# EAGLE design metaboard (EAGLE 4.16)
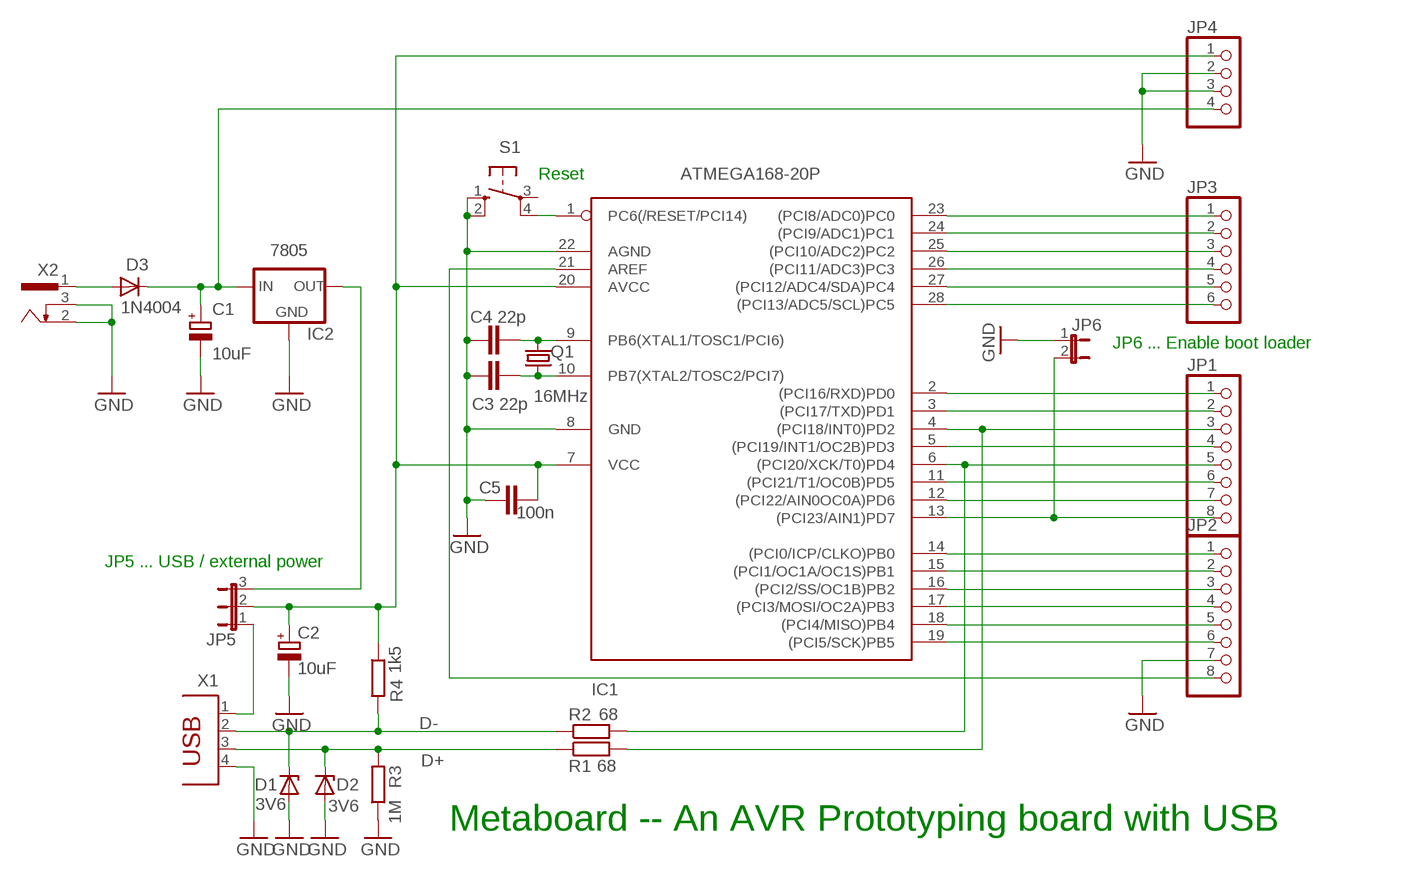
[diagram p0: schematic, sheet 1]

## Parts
C1  10uF  CPOL-EUE2,5-6E  [E2,5-6E]
C2  10uF  CPOL-EUE2,5-6E  [E2,5-6E]
C3  22p  C-EU025-024X044  [C025-024X044]
C4  22p  C-EU025-024X044  [C025-024X044]
C5  100n  C-EU025_050-025X075  [C025_050-025X075]
D1  3V6  ZENER-DIODEDO34-7  [DO34Z7]
D2  3V6  ZENER-DIODEDO34-7  [DO34Z7]
D3  1N4004  [DO41-10]
IC1  ATMEGA168-20P  [DIL28-3]
IC2  7805  78XXL  [78XXL]
JP1  PINHD-1X8  [1X08]
JP2  PINHD-1X8  [1X08]
JP3  PINHD-1X6  [1X06]
JP4  PINHD-1X4  [1X04]
JP5  JP2E  [JP2]
JP6  JP1E  [JP1]
Q1  16MHz  CRYSTALHC49S  [HC49/S]
R1  68  R-EU_0207/10  [0207/10]
R2  68  R-EU_0207/10  [0207/10]
R3  1M  R-EU_0207/10  [0207/10]
R4  1k5  R-EU_0207/10  [0207/10]
S1  10-XX  [B3F-10XX]
X1  PN61729  [PN61729]
X2  733980-62  [733980-62]

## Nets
+5USB: JP5.1 X1.1
+5V: C2.+ C5.2 IC1.7(VCC) IC1.20(AVCC) JP4.1 JP5.2 R4.1
+VRAW: C1.+ D3.C IC2.IN JP4.4
D+: D2.C R1.1 R3.2 X1.3
D-: D1.C R2.1 R4.2 X1.2
GND: C1.- C2.- C3.1 C4.1 C5.1 D1.A D2.A IC1.8(GND) IC1.22(AGND) IC2.GND JP2.7 JP4.2 JP4.3 JP6.1 R3.1 S1.1(S) S1.2(S1) X1.4 X2.2 X2.3
N$1: IC1.6((PCI20/XCK/T0)PD4) JP1.5 R2.2
N$2: IC1.1(PC6(/RESET/PCI14)) S1.4(P1)
N$3: IC1.4((PCI18/INT0)PD2) JP1.3 R1.2
N$4: D3.A X2.1
N$6: IC1.2((PCI16/RXD)PD0) JP1.1
N$8: IC2.OUT JP5.3
N$9: C3.2 IC1.10(PB7(XTAL2/TOSC2/PCI7)) Q1.1
N$10: C4.2 IC1.9(PB6(XTAL1/TOSC1/PCI6)) Q1.2
N$11: IC1.3((PCI17/TXD)PD1) JP1.2
N$12: IC1.5((PCI19/INT1/OC2B)PD3) JP1.4
N$13: IC1.11((PCI21/T1/OC0B)PD5) JP1.6
N$14: IC1.12((PCI22/AIN0OC0A)PD6) JP1.7
N$15: IC1.13((PCI23/AIN1)PD7) JP1.8 JP6.2
N$16: IC1.23((PCI8/ADC0)PC0) JP3.1
N$17: IC1.24((PCI9/ADC1)PC1) JP3.2
N$18: IC1.25((PCI10/ADC2)PC2) JP3.3
N$19: IC1.26((PCI11/ADC3)PC3) JP3.4
N$20: IC1.27((PCI12/ADC4/SDA)PC4) JP3.5
N$21: IC1.28((PCI13/ADC5/SCL)PC5) JP3.6
N$22: IC1.14((PCI0/ICP/CLKO)PB0) JP2.1
N$23: IC1.15((PCI1/OC1A/OC1S)PB1) JP2.2
N$24: IC1.16((PCI2/SS/OC1B)PB2) JP2.3
N$25: IC1.17((PCI3/MOSI/OC2A)PB3) JP2.4
N$26: IC1.18((PCI4/MISO)PB4) JP2.5
N$27: IC1.19((PCI5/SCK)PB5) JP2.6
N$28: IC1.21(AREF) JP2.8
Unconnected: S1.3(P)

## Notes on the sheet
- Reset
- JP6 ... Enable boot loader
- JP5 ... USB / external power
- Metaboard -- An AVR Prototyping board with USB

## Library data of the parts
C1 C2 = rcl:CPOL-EU: POLARIZED CAPACITOR, European symbol
C3-C5 = rcl:C-EU: CAPACITOR, European symbol
D1 D2 = diode:ZENER-DIODE: Z-Diode
D3 = diode:1N4004: DIODE
IC1 = avr:ATMEGA168*P: MICROCONTROLLER 16 kBytes FLASH 1 kBytes SRAM 512 Bytes EEPROM USART 8-channel 10 bit ADC
IC2 = v-reg:78XXL: VOLTAGE REGULATOR
JP1 JP2 = pinhead:PINHD-1X8: PIN HEADER
JP3 = pinhead:PINHD-1X6: PIN HEADER
JP4 = pinhead:PINHD-1X4: PIN HEADER
JP5 = jumper:JP2E: JUMPER
JP6 = jumper:JP1E: JUMPER
Q1 = crystal:CRYSTAL: CRYSTAL
R1-R4 = rcl:R-EU_: RESISTOR, European symbol
S1 = switch-omron:10-XX: OMRON SWITCH
X1 = con-berg:PN61729: BERG USB connector
X2 = con-conrad:73398?: FEMALE PRINT CONNECTOR Niedervolt-Steckverbinder Distributor Conrad

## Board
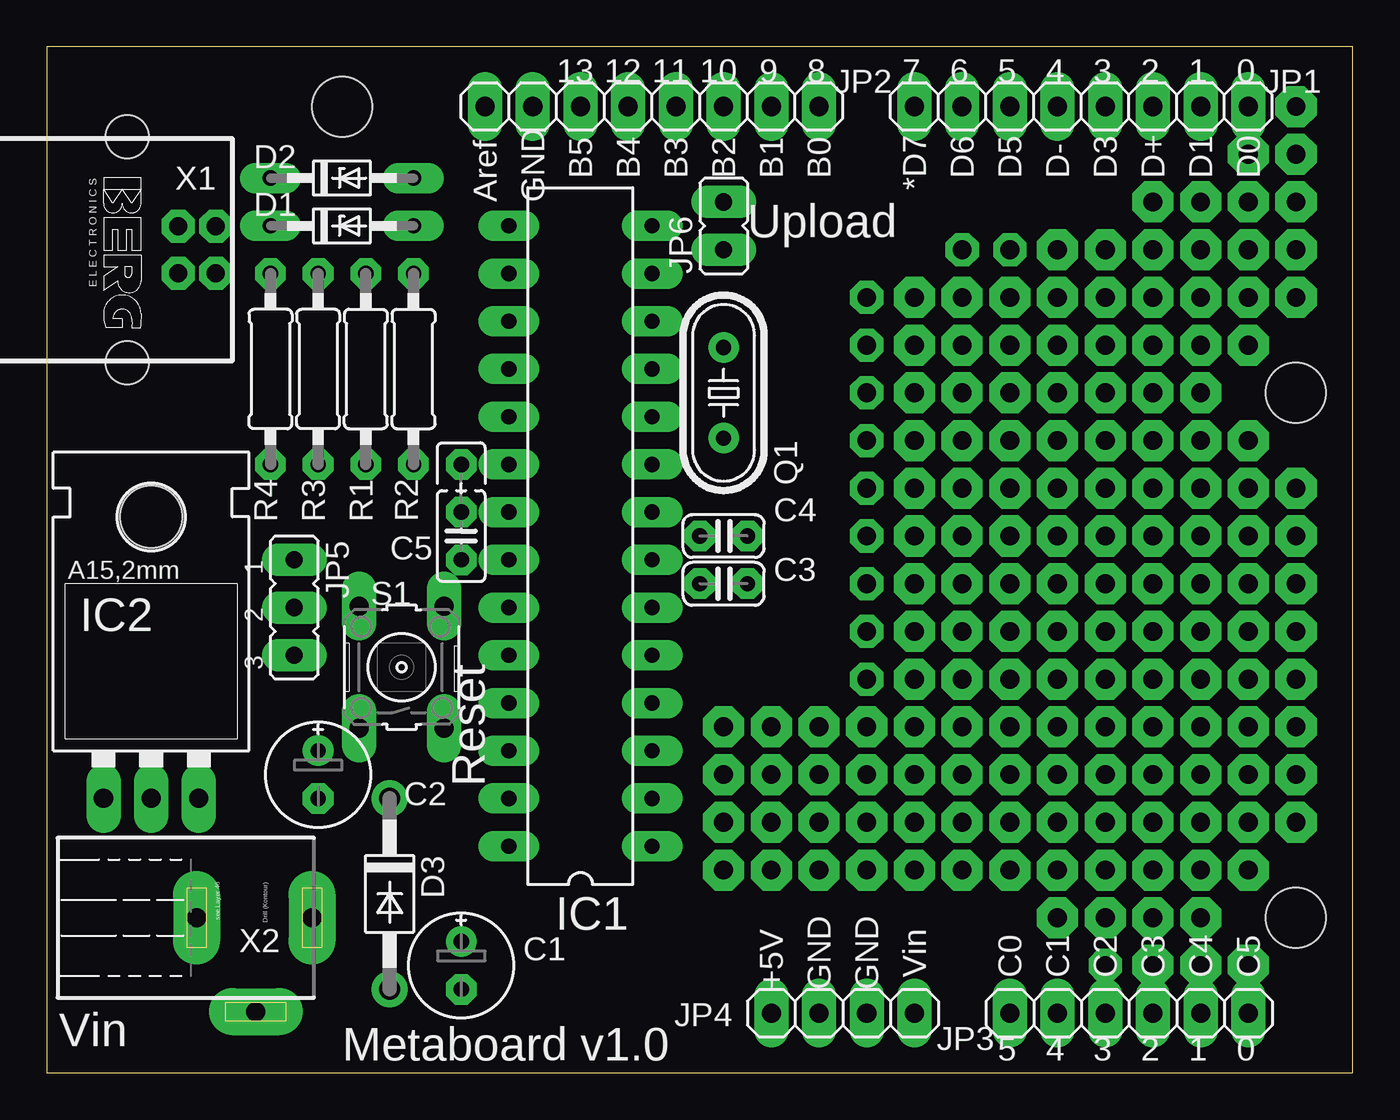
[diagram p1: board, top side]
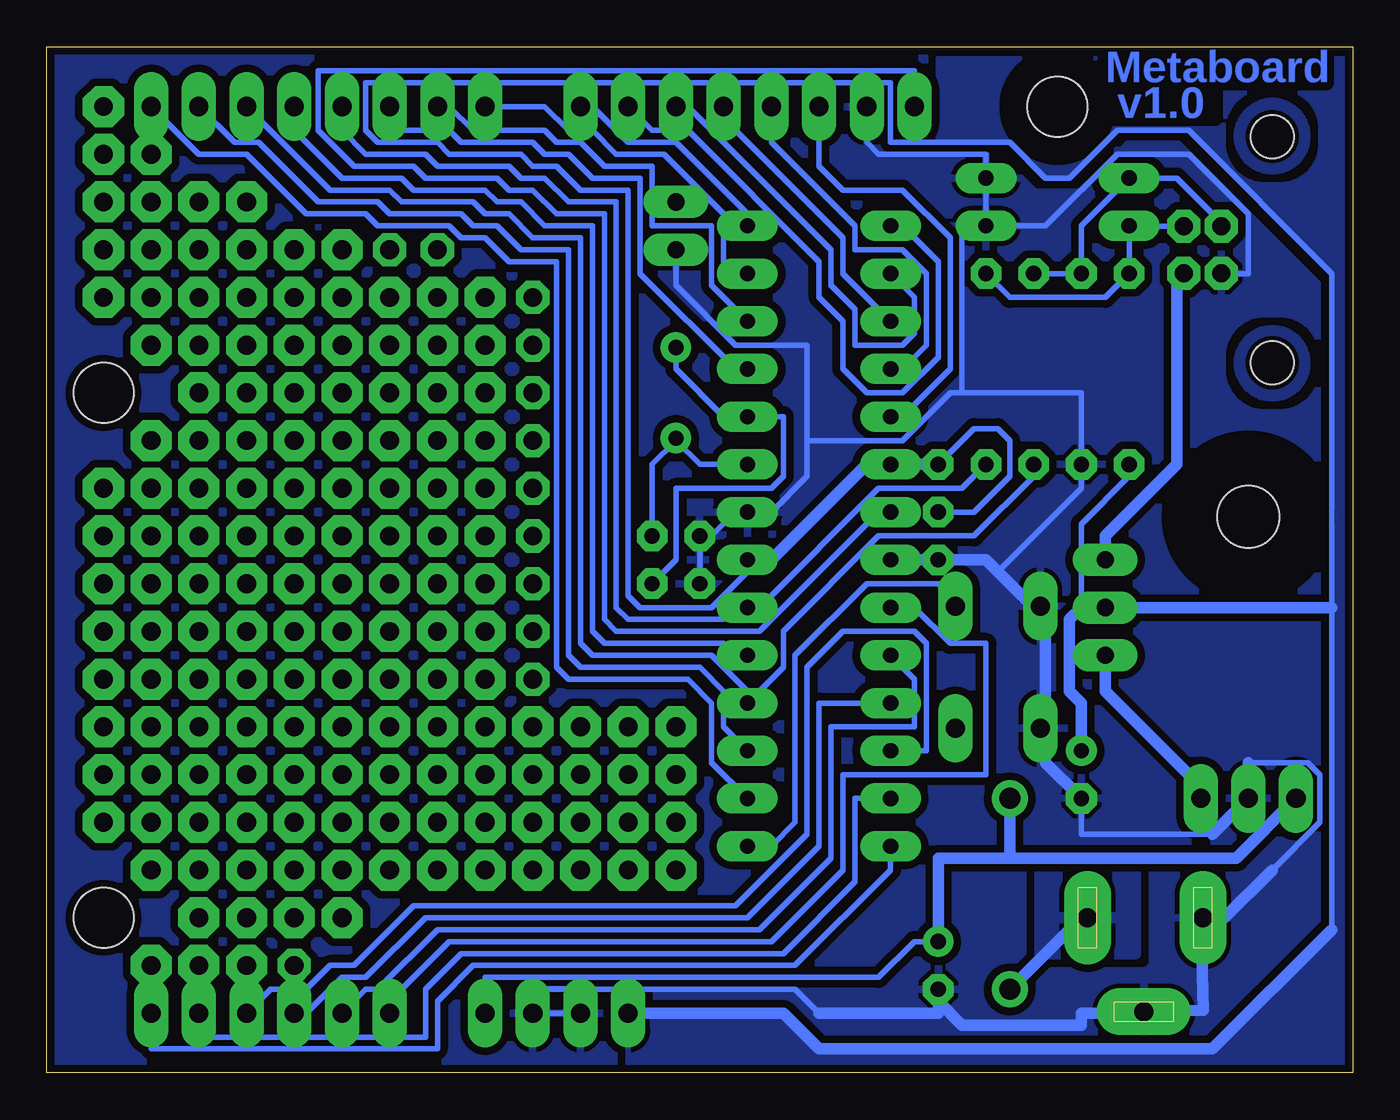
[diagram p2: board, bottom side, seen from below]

Size 69.52 x 54.6 mm. Coordinates in mm from the lower left corner, seen from the top.
Outline: 0,0 69.52,0 69.52,54.6 0,54.6 0,0
Copper layers (1*16): Top 0.035mm / dielectric 1.5mm / Bottom 0.035mm
Design rules "mine": minimum track width 12mil, minimum drill 31mil, track to track 8mil, track to pad 8mil, pad to pad 8mil, via to via 8mil, smd to smd 8mil, copper to edge 10mil, drill to drill 20mil, minimum pad ring 16mil, minimum via ring 15mil, stop-mask expansion 4mil, vias tented up to drill 0mil, thermal gap 10mil
Holes 3.2 mm at 66.51,36.19 66.51,8.25 15.71,51.43
bRestrict: area 13,48.7 to 18.4,54.1

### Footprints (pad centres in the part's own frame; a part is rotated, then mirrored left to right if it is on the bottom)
E2,5-6E = drill 0.813 pad 1.575 round: + -1.27,0 | drill 0.813 pad 1.575 octagon: - 1.27,0
C025-024X044 = drill 0.813 octagon: 1 -1.27,0; 2 1.27,0
C025_050-025X075 = drill 0.813 octagon: 1 -1.27,0; 2 1.27,0; 3 3.81,0
DO34Z7 = drill 0.813 long: A 3.81,0; C -3.81,0
DO41-10 = drill 1.118 round: A 5.08,0; C -5.08,0
DIL28-3 = drill 0.813 long: 1 -16.51,-3.81; 2 -13.97,-3.81; 3 -11.43,-3.81; 4 -8.89,-3.81; 5 -6.35,-3.81; 6 -3.81,-3.81; 7 -1.27,-3.81; 8 1.27,-3.81; 9 3.81,-3.81; 10 6.35,-3.81; 11 8.89,-3.81; 12 11.43,-3.81; 13 13.97,-3.81; 14 16.51,-3.81; 15 16.51,3.81; 16 13.97,3.81; 17 11.43,3.81; 18 8.89,3.81; 19 6.35,3.81; 20 3.81,3.81; 21 1.27,3.81; 22 -1.27,3.81; 23 -3.81,3.81; 24 -6.35,3.81; 25 -8.89,3.81; 26 -11.43,3.81; 27 -13.97,3.81; 28 -16.51,3.81
78XXL = drill 1.016 long: GND 0,-3.81; IN -2.54,-3.81; OUT 2.54,-3.81 | hole 3.302: 0,11.176
1X08 = drill 1.016 long: 1 -8.89,0; 2 -6.35,0; 3 -3.81,0; 4 -1.27,0; 5 1.27,0; 6 3.81,0; 7 6.35,0; 8 8.89,0
1X06 = drill 1.016 long: 1 -6.35,0; 2 -3.81,0; 3 -1.27,0; 4 1.27,0; 5 3.81,0; 6 6.35,0
1X04 = drill 1.016 long: 1 -3.81,0; 2 -1.27,0; 3 1.27,0; 4 3.81,0
JP2 = drill 0.914 long: 1 -2.54,0; 2 0,0; 3 2.54,0
JP1 = drill 0.914 long: 1 0,-1.27; 2 0,1.27
HC49/S = drill 0.813 round: 1 -2.413,0; 2 2.413,0
0207/10 = drill 0.813 octagon: 1 -5.08,0; 2 5.08,0
B3F-10XX = drill 1.016 long: 1 -3.251,2.261; 2 3.251,2.261; 3 -3.251,-2.261; 4 3.251,-2.261
PN61729 = drill 0.95 octagon: 1 1.25,4.71; 2 -1.25,4.71; 3 -1.25,2.71; 4 1.25,2.71 | hole 2.3: -6.02,0; 6.02,0
733980-62 = drill 1 pad 2.5 long: 1 0,8.57; 2 0,2.42; 3 5,5.57

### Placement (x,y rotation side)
C1  22.06,5.71 270 top
C2  14.44,15.87 270 top
C3  36.03,26.03 0 top
C4  36.03,28.57 0 top
C5  22.06,28.57 90 top
D1  15.71,45.08 0 top
D2  15.71,47.62 0 top
D3  18.25,9.52 270 top
IC1  28.41,28.57 90 top
IC2  5.55,18.41 0 top
JP1  55.08,51.43 180 top
JP2  32.22,51.43 180 top
JP3  57.62,3.17 0 top
JP4  42.38,3.17 0 top
JP5  13.17,24.76 270 top
JP6  36.03,45.08 0 top
Q1  36.03,36.19 270 top
R1  16.98,37.46 270 top
R2  19.52,37.46 270 top
R3  14.44,37.46 90 top
R4  11.9,37.46 90 top
S1  18.88,21.58 90 top
X1  4.28,43.81 270 top
X2  5.55,8.25 270 top

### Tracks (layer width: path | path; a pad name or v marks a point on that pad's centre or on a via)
+5USB
  Bottom 0.61: JP5.1 13.17,28.57 9.36,32.38 9.36,41.91 X1.1
+5V
  Bottom 0.305: IC1.7 32.22,26.66 34.12,24.76 37.94,24.76 38.57,25.39 38.57,46.98 41.11,46.98 42.38,48.26 43.65,48.26 44.28,48.89 48.09,48.89 48.73,49.53 51.91,49.53 52.54,50.16 52.54,52.7 24.6,52.7 24.6,49.53 18.25,49.53 16.34,47.62 15.08,47.62 12.54,50.16 8.73,50.16 1.1,42.54 1.1,24.76 1.1,7.62 | 14.44,24.76 14.44,29.2 11.9,31.74 R4.1 | C5.2 20.15,29.84 18.25,31.74 18.25,33.65 18.88,34.29 20.15,34.29 22.06,32.38
  Bottom 0.61: IC1.7 30.95,27.3 25.87,32.38 IC1.20 22.06,32.38 | JP4.1 30.31,3.17 28.41,1.27 7.46,1.27 1.1,7.62 | C2.+ 14.44,19.68 15.08,20.31 15.08,24.12 14.44,24.76 JP5.2 1.1,24.76
  pour Bottom (isolate 0.406): 0.47,42.54 0.47,7.62 1.1,7.62 1.1,42.54
  pour Bottom (isolate 0.406, rank 2): 0.47,42.54 0.47,53.97 22.06,53.97 22.06,49.53 18.25,49.53 16.34,47.62 15.08,47.62 12.54,50.16 8.73,50.16 1.1,42.54
  pour Bottom (isolate 0.406, rank 2): 1.74,6.98 7.46,1.27 28.41,1.27 30.31,3.17 38.57,3.17 38.57,-0.01 -0.17,-0.01 -0.17,7.62 1.1,7.62
+VRAW
  Bottom 0.305: JP4.4 46.19,5.08 25.23,5.08 23.33,6.98 C1.+
  Bottom 0.61: IC2.IN 6.18,11.43 18.25,11.43 | 18.25,11.43 22.06,11.43 C1.+ | 18.25,11.43 D3.C
D+
  Bottom 0.305: R1.1 R3.2 14.44,45.08 D2.C 9.36,47.62 6.99,45.25 X1.3
D-
  Bottom 0.305: R2.1 18.25,41.27 13.17,41.27 R4.2 11.88,42.56 11.88,45.06 | 11.88,45.06 X1.2 | 11.88,45.06 D1.C
GND
  Bottom 0.305: C5.1 IC1.22 | JP4.3 JP4.2 41.11,4.44 29.68,4.44 28.41,3.17 | C2.- 14.44,12.7 7.46,12.7 | 5.55,16.5 2.38,16.5 1.74,15.87 1.74,13.33 4.28,10.79 | C3.1 C4.1 34.12,28.57 32.85,29.84 IC1.8 30.95,29.84 29.04,31.74 29.04,33.65 | JP6.1 36.03,41.91 32.85,38.73 29.04,38.73 29.04,33.65 | 29.04,33.65 23.96,33.65 21.42,36.19 20.79,36.19 | JP2.7 25.87,49.53 25.23,48.89 19.52,48.89 D2.A | 20.79,36.19 14.44,36.19 R3.1 14.44,31.11 18.88,26.66 | 20.79,36.19 20.79,45.08 D1.A | D1.A D2.A | D1.A D2.A | D1.A 16.34,45.08 12.54,48.89 8.73,48.89 5.55,45.72 5.55,42.54 6.82,42.54 X1.4
  Bottom 0.308: 41.11,4.44 43.65,4.44 JP4.3
  Bottom 0.61: IC1.22 C5.1 19.52,27.3 18.88,26.66 16.98,24.76 | S1.2 16.9,24.84 16.98,24.76 | 16.98,24.76 16.34,24.12 16.34,18.41 | S1.1 16.42,18.33 16.34,18.41 | 16.34,18.41 16.34,16.5 C2.- | 28.41,3.17 22.06,3.17 C1.- 22.06,3.8 20.79,2.54 14.44,2.54 14.44,3.17 11.27,3.17 11.19,3.25 X2.3 7.94,3.31 8.09,8.25 | 7.46,12.7 IC2.GND 5.55,16.5 | 4.28,10.79 6.82,8.25 8.09,8.25 | 8.09,8.25 X2.2
  pour Bottom (isolate 0.406, rank 3): -0.17,54.61 69.69,54.61 69.69,-0.01 -0.17,-0.01
N$1
  Bottom 0.305: JP1.5 53.81,50.16 52.54,48.89 49.37,48.89 48.73,48.26 44.92,48.26 44.28,47.62 43.02,47.62 41.74,46.35 39.2,46.35 39.2,24.76 38.57,24.12 33.49,24.12 32.85,24.76 IC1.6 31.58,24.76 25.23,31.11 20.79,31.11 R2.2
N$2
  Bottom 0.305: IC1.1 30.95,12.06 29.68,13.33 29.68,22.22 25.87,26.03 22.06,26.03 21.42,25.39 S1.4
N$3
  Bottom 0.305: JP1.3 54.45,46.98 51.27,46.98 50.63,46.35 46.82,46.35 46.19,45.72 44.92,45.72 43.65,44.45 41.11,44.45 41.11,22.86 40.48,22.22 34.12,22.22 32.22,20.31 IC1.4 30.31,21.58 30.31,23.49 25.23,28.57 20.15,28.57 16.98,31.74 R1.2
N$4
  Bottom 0.61: X2.1 14.44,8.25 D3.A
  pour Bottom (isolate 0.406): 11.57,10.79 16.65,10.79 16.65,6.34 11.57,6.34
N$5  (via drill 1 pad 2.18)
  other vias: 63.97,48.89
N$6
  Bottom 0.305: IC1.2 34.12,16.5 34.12,19.68 35.39,20.95 41.74,20.95 42.38,21.58 42.38,43.18 44.92,43.18 46.19,44.45 47.46,44.45 48.09,45.08 51.91,45.08 52.54,45.72 55.71,45.72 58.89,48.89 61.43,48.89 JP1.1
N$7  (via drill 1 pad 2.18)
  other vias: 63.97,46.35
N$8
  Bottom 0.61: JP5.3 13.17,20.31 8.09,15.24 IC2.OUT
N$9
  Bottom 0.305: 36.03,38.73 Q1.1 36.03,37.46 33.49,34.92 IC1.10 30.31,34.92 30.31,31.74 30.95,31.11 36.03,31.11 36.03,27.3 C3.2
N$10
  Bottom 0.305: IC1.9 34.76,32.38 36.03,33.65 | 36.03,33.65 Q1.2 | C4.2 37.3,32.38 36.03,33.65
N$11
  Bottom 0.305: IC1.3 33.49,18.41 33.49,20.31 34.76,21.58 41.11,21.58 41.74,22.22 41.74,43.81 44.28,43.81 45.55,45.08 46.82,45.08 47.46,45.72 51.27,45.72 51.91,46.35 55.08,46.35 58.25,49.53 59.52,49.53 JP1.2
N$12
  Bottom 0.305: IC1.5 32.85,22.22 33.49,22.86 39.84,22.86 40.48,23.49 40.48,45.08 43.02,45.08 44.28,46.35 45.55,46.35 46.19,46.98 50,46.98 50.63,47.62 53.81,47.62 56.35,50.16 JP1.4
N$13
  Bottom 0.305: JP1.6 51.27,50.16 48.09,50.16 47.46,49.53 43.65,49.53 43.02,48.89 41.74,48.89 40.48,47.62 37.94,47.62 37.94,42.54 32.85,37.46 IC1.11
N$14
  Bottom 0.305: JP1.7 48.09,51.43 46.82,50.16 43.02,50.16 42.38,49.53 41.11,49.53 39.84,48.26 37.3,48.26 37.3,45.08 34.12,45.08 34.12,41.91 IC1.12
N$15
  Bottom 0.305: IC1.13 33.49,42.54 33.49,45.72 34.76,46.98 | JP1.8 43.02,51.43 41.74,50.16 40.48,50.16 39.2,48.89 36.66,48.89 34.76,46.98 | JP6.2 35.39,46.35 34.76,46.98
N$16
  Bottom 0.305: IC1.23 23.33,24.76 21.42,22.86 19.52,22.86 19.52,15.87 27.14,15.87 27.14,10.79 30.95,6.98 48.09,6.98 51.27,3.8 JP3.1
N$17
  Bottom 0.305: IC1.24 23.33,20.95 23.33,18.41 27.77,18.41 27.77,11.43 31.58,7.62 48.73,7.62 51.91,4.44 52.54,4.44 JP3.2
N$18
  Bottom 0.305: JP3.3 55.71,3.17 53.81,5.08 52.54,5.08 49.37,8.25 32.22,8.25 28.41,12.06 28.41,19.68 IC1.25
N$19
  Bottom 0.305: IC1.26 22.7,17.14 22.7,22.86 23.33,23.49 27.14,23.49 29.04,21.58 29.04,12.7 32.85,8.89 50,8.89 53.17,5.71 54.45,5.71 55.71,4.44 57.62,4.44 JP3.4
N$20
  Bottom 0.305: IC1.27 26.5,14.6 26.5,10.16 30.31,6.34 47.46,6.34 49.37,4.44 49.37,1.9 61.43,1.9 JP3.5
N$21
  Bottom 0.305: IC1.28 24.6,10.79 29.68,5.71 46.82,5.71 48.73,3.8 48.73,1.27 63.97,1.27 JP3.6
N$22
  Bottom 0.305: IC1.14 32.22,45.72 36.03,49.53 38.57,49.53 40.48,51.43 JP2.1
N$23
  Bottom 0.305: JP2.2 37.3,50.16 35.39,50.16 28.41,43.18 28.41,41.27 27.14,40 27.14,37.46 25.87,36.19 23.96,36.19 22.06,38.1 22.06,43.18 23.96,45.08 IC1.15
N$24
  Bottom 0.305: JP2.3 35.39,51.43 27.77,43.81 27.77,41.91 26.5,40.64 26.5,38.73 23.96,38.73 23.33,39.37 23.33,41.27 IC1.16
N$25
  Bottom 0.305: IC1.17 27.14,42.54 27.14,44.45 33.49,50.8 JP2.4
N$26
  Bottom 0.305: IC1.18 23.96,37.46 22.7,38.73 22.7,42.54 23.96,43.81 26.5,43.81 26.5,45.08 30.95,49.53 JP2.5
N$27
  Bottom 0.305: IC1.19 23.96,34.92 21.42,37.46 21.42,44.45 23.96,46.98 27.14,46.98 28.41,48.26 JP2.6
N$28
  Bottom 0.305: IC1.21 25.23,29.84 31.58,23.49 39.2,23.49 39.84,24.12 39.84,45.72 42.38,45.72 43.65,46.98 44.92,46.98 45.55,47.62 49.37,47.62 50,48.26 53.17,48.26 55.08,50.16 55.08,53.34 23.33,53.34 JP2.8
N$29  (via drill 1 pad 2.18)
  other vias: 63.97,43.81
N$30  (via drill 1 pad 2.18)
  other vias: 63.97,41.27
N$31  (via drill 1 pad 2.18)
  other vias: 66.51,41.27
N$32  (via drill 1 pad 2.18)
  other vias: 66.51,43.81
N$33  (via drill 1 pad 2.18)
  other vias: 66.51,46.35
N$34  (via drill 1 pad 2.18)
  other vias: 66.51,48.89
N$35  (via drill 1 pad 2.18)
  other vias: 63.97,38.73
N$36  (via drill 1 pad 2.18)
  other vias: 61.43,38.73
N$37  (via drill 1 pad 2.18)
  other vias: 61.43,41.27
N$38  (via drill 1 pad 2.18)
  other vias: 61.43,43.81
N$39  (via drill 1 pad 2.18)
  other vias: 61.43,46.35
N$40  (via drill 1 pad 2.18)
  other vias: 58.89,46.35
N$41  (via drill 1 pad 2.18)
  other vias: 58.89,43.81
N$42  (via drill 1 pad 2.18)
  other vias: 58.89,41.27
N$43  (via drill 1 pad 2.18)
  other vias: 58.89,38.73
N$44  (via drill 1 pad 2.18)
  other vias: 56.35,38.73
N$45  (via drill 1 pad 2.18)
  other vias: 56.35,41.27
N$46  (via drill 1 pad 2.18)
  other vias: 56.35,43.81
N$47  (via drill 1 pad 2.18)
  other vias: 53.81,41.27
N$48  (via drill 1 pad 2.18)
  other vias: 53.81,38.73
N$49  (via drill 1 pad 2.18)
  other vias: 51.27,38.73
N$50  (via drill 1 pad 2.18)
  other vias: 51.27,41.27
N$51  (via drill 1 pad 2.18)
  other vias: 48.73,41.27
N$52  (via drill 1 pad 2.18)
  other vias: 46.19,41.27
N$53  (via drill 1 pad 2.18)
  other vias: 46.19,38.73
N$54  (via drill 1 pad 2.18)
  other vias: 48.73,38.73
N$55  (via drill 1 pad 2.18)
  other vias: 46.19,36.19
N$56  (via drill 1 pad 2.18)
  other vias: 48.73,36.19
N$57  (via drill 1 pad 2.18)
  other vias: 51.27,36.19
N$58  (via drill 1 pad 2.18)
  other vias: 53.81,36.19
N$59  (via drill 1 pad 2.18)
  other vias: 56.35,36.19
N$60  (via drill 1 pad 2.18)
  other vias: 58.89,36.19
N$61  (via drill 1 pad 2.18)
  other vias: 61.43,36.19
N$62  (via drill 1)
  other vias: 56.35,5.71
N$63  (via drill 1 pad 2.18)
  other vias: 46.19,26.03
N$64  (via drill 1 pad 2.18)
  other vias: 46.19,33.65
N$65  (via drill 1 pad 2.18)
  other vias: 48.73,33.65
N$66  (via drill 1 pad 2.18)
  other vias: 51.27,33.65
N$67  (via drill 1 pad 2.18)
  other vias: 53.81,33.65
N$68  (via drill 1 pad 2.18)
  other vias: 56.35,33.65
N$69  (via drill 1 pad 2.18)
  other vias: 58.89,33.65
N$70  (via drill 1 pad 2.18)
  other vias: 61.43,33.65
N$71  (via drill 1 pad 2.18)
  other vias: 63.97,33.65
N$72  (via drill 1)
  other vias: 43.65,41.27
N$73  (via drill 1 pad 2.18)
  other vias: 46.19,31.11
N$74  (via drill 1 pad 2.18)
  other vias: 48.73,31.11
N$75  (via drill 1 pad 2.18)
  other vias: 51.27,31.11
N$76  (via drill 1 pad 2.18)
  other vias: 53.81,31.11
N$77  (via drill 1 pad 2.18)
  other vias: 56.35,31.11
N$78  (via drill 1 pad 2.18)
  other vias: 58.89,31.11
N$79  (via drill 1 pad 2.18)
  other vias: 61.43,31.11
N$80  (via drill 1 pad 2.18)
  other vias: 63.97,31.11
N$81  (via drill 1 pad 2.18)
  other vias: 66.51,31.11
N$82  (via drill 1 pad 2.18)
  other vias: 46.19,28.57
N$83  (via drill 1 pad 2.18)
  other vias: 48.73,28.57
N$84  (via drill 1 pad 2.18)
  other vias: 51.27,28.57
N$85  (via drill 1 pad 2.18)
  other vias: 53.81,28.57
N$86  (via drill 1 pad 2.18)
  other vias: 56.35,28.57
N$87  (via drill 1 pad 2.18)
  other vias: 58.89,28.57
N$88  (via drill 1 pad 2.18)
  other vias: 61.43,28.57
N$89  (via drill 1 pad 2.18)
  other vias: 63.97,28.57
N$90  (via drill 1 pad 2.18)
  other vias: 66.51,28.57
N$91  (via drill 1 pad 2.18)
  other vias: 66.51,26.03
N$92  (via drill 1 pad 2.18)
  other vias: 63.97,26.03
N$93  (via drill 1 pad 2.18)
  other vias: 61.43,26.03
N$94  (via drill 1 pad 2.18)
  other vias: 58.89,26.03
N$95  (via drill 1 pad 2.18)
  other vias: 56.35,26.03
N$96  (via drill 1 pad 2.18)
  other vias: 53.81,26.03
N$97  (via drill 1 pad 2.18)
  other vias: 51.27,26.03
N$98  (via drill 1 pad 2.18)
  other vias: 48.73,26.03
N$99  (via drill 1)
  other vias: 43.65,38.73
N$100  (via drill 1 pad 2.18)
  other vias: 46.19,23.49
N$101  (via drill 1 pad 2.18)
  other vias: 48.73,23.49
N$102  (via drill 1 pad 2.18)
  other vias: 51.27,23.49
N$103  (via drill 1 pad 2.18)
  other vias: 53.81,23.49
N$104  (via drill 1 pad 2.18)
  other vias: 56.35,23.49
N$105  (via drill 1 pad 2.18)
  other vias: 58.89,23.49
N$106  (via drill 1 pad 2.18)
  other vias: 61.43,23.49
N$107  (via drill 1 pad 2.18)
  other vias: 63.97,23.49
N$108  (via drill 1 pad 2.18)
  other vias: 66.51,23.49
N$109  (via drill 1 pad 2.18)
  other vias: 46.19,20.95
N$110  (via drill 1 pad 2.18)
  other vias: 48.73,20.95
N$111  (via drill 1 pad 2.18)
  other vias: 51.27,20.95
N$112  (via drill 1 pad 2.18)
  other vias: 53.81,20.95
N$113  (via drill 1 pad 2.18)
  other vias: 56.35,20.95
N$114  (via drill 1 pad 2.18)
  other vias: 58.89,20.95
N$115  (via drill 1 pad 2.18)
  other vias: 61.43,20.95
N$116  (via drill 1 pad 2.18)
  other vias: 63.97,20.95
N$117  (via drill 1 pad 2.18)
  other vias: 66.51,20.95
N$118  (via drill 1 pad 2.18)
  other vias: 66.51,18.41
N$119  (via drill 1 pad 2.18)
  other vias: 63.97,18.41
N$120  (via drill 1 pad 2.18)
  other vias: 61.43,18.41
N$121  (via drill 1 pad 2.18)
  other vias: 58.89,18.41
N$122  (via drill 1 pad 2.18)
  other vias: 56.35,18.41
N$123  (via drill 1 pad 2.18)
  other vias: 53.81,18.41
N$124  (via drill 1 pad 2.18)
  other vias: 51.27,18.41
N$125  (via drill 1 pad 2.18)
  other vias: 48.73,18.41
N$126  (via drill 1 pad 2.18)
  other vias: 46.19,18.41
N$127  (via drill 1 pad 2.18)
  other vias: 43.65,18.41
N$128  (via drill 1 pad 2.18)
  other vias: 41.11,18.41
N$129  (via drill 1 pad 2.18)
  other vias: 38.57,18.41
N$130  (via drill 1 pad 2.18)
  other vias: 36.03,18.41
N$131  (via drill 1 pad 2.18)
  other vias: 36.03,15.87
N$132  (via drill 1 pad 2.18)
  other vias: 38.57,15.87
N$133  (via drill 1 pad 2.18)
  other vias: 41.11,15.87
N$134  (via drill 1 pad 2.18)
  other vias: 43.65,15.87
N$135  (via drill 1 pad 2.18)
  other vias: 46.19,15.87
N$136  (via drill 1 pad 2.18)
  other vias: 48.73,15.87
N$137  (via drill 1 pad 2.18)
  other vias: 51.27,15.87
N$138  (via drill 1 pad 2.18)
  other vias: 53.81,15.87
N$139  (via drill 1 pad 2.18)
  other vias: 56.35,15.87
N$140  (via drill 1 pad 2.18)
  other vias: 58.89,15.87
N$141  (via drill 1 pad 2.18)
  other vias: 61.43,15.87
N$142  (via drill 1 pad 2.18)
  other vias: 63.97,15.87
N$143  (via drill 1 pad 2.18)
  other vias: 66.51,15.87
N$144  (via drill 1 pad 2.18)
  other vias: 66.51,13.33
N$145  (via drill 1 pad 2.18)
  other vias: 63.97,13.33
N$146  (via drill 1 pad 2.18)
  other vias: 61.43,13.33
N$147  (via drill 1 pad 2.18)
  other vias: 58.89,13.33
N$148  (via drill 1 pad 2.18)
  other vias: 56.35,13.33
N$149  (via drill 1 pad 2.18)
  other vias: 53.81,13.33
N$150  (via drill 1 pad 2.18)
  other vias: 51.27,13.33
N$151  (via drill 1 pad 2.18)
  other vias: 48.73,13.33
N$152  (via drill 1 pad 2.18)
  other vias: 46.19,13.33
N$153  (via drill 1 pad 2.18)
  other vias: 43.65,13.33
N$154  (via drill 1 pad 2.18)
  other vias: 41.11,13.33
N$155  (via drill 1 pad 2.18)
  other vias: 38.57,13.33
N$156  (via drill 1 pad 2.18)
  other vias: 36.03,13.33
N$157  (via drill 1 pad 2.18)
  other vias: 36.03,10.79
N$158  (via drill 1 pad 2.18)
  other vias: 38.57,10.79
N$159  (via drill 1 pad 2.18)
  other vias: 41.11,10.79
N$160  (via drill 1 pad 2.18)
  other vias: 43.65,10.79
N$161  (via drill 1 pad 2.18)
  other vias: 46.19,10.79
N$162  (via drill 1 pad 2.18)
  other vias: 48.73,10.79
N$163  (via drill 1 pad 2.18)
  other vias: 51.27,10.79
N$164  (via drill 1 pad 2.18)
  other vias: 53.81,10.79
N$165  (via drill 1 pad 2.18)
  other vias: 56.35,10.79
N$166  (via drill 1 pad 2.18)
  other vias: 58.89,10.79
N$167  (via drill 1 pad 2.18)
  other vias: 61.43,10.79
N$168  (via drill 1 pad 2.18)
  other vias: 63.97,10.79
N$169  (via drill 1)
  other vias: 43.65,36.19
N$170  (via drill 1)
  other vias: 43.65,33.65
N$171  (via drill 1 pad 2.18)
  other vias: 61.43,8.25
N$172  (via drill 1 pad 2.18)
  other vias: 58.89,8.25
N$173  (via drill 1 pad 2.18)
  other vias: 56.35,8.25
N$174  (via drill 1 pad 2.18)
  other vias: 53.81,8.25
N$175  (via drill 1 pad 2.18)
  other vias: 61.43,5.71
N$176  (via drill 1 pad 2.18)
  other vias: 63.97,5.71
N$177  (via drill 1 pad 2.18)
  other vias: 58.89,5.71
N$178  (via drill 1)
  other vias: 43.65,31.11
N$179  (via drill 1 pad 2.18)
  other vias: 66.51,51.43
N$180  (via drill 1 pad 2.18)
  other vias: 53.81,43.81
N$181  (via drill 1)
  other vias: 51.27,43.81
N$182  (via drill 1)
  other vias: 43.65,28.57
N$183  (via drill 1)
  other vias: 43.65,26.03
N$184  (via drill 1)
  other vias: 43.65,23.49
N$185  (via drill 1)
  other vias: 43.65,20.95
N$186  (via drill 1)
  other vias: 48.73,43.81
N$187
  pour Bottom (isolate 2.54, no thermals): 43.65,41.27 46.19,41.27 48.73,43.81 56.35,43.81 58.89,46.35 61.43,46.35 67.78,52.7 67.78,5.71 56.35,5.71 51.27,10.79 36.03,10.79 36.03,18.41 41.11,18.41 43.65,20.95
N$188
  pour Bottom: 4.28,51.76 arc-90 6.18,49.86 arc-90 4.28,47.95 arc-90 2.38,49.86 arc-90
  pour Bottom: 4.28,39.67 arc-90 6.18,37.76 arc-90 4.28,35.86 arc-90 2.38,37.76 arc-90

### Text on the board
Bottom: Metaboard | v1.0
tPlace: 13 | 12 | 11 | 10 | 9 | 8 | 7 | 6 | 5 | 4 | 3 | 2 | 1 | 0 | B5 | B4 | B3 | B2 | B1 | B0 | D6 | D5 | D- | D3 | D+ | D1 | D0 | Aref | GND | *D7 | Upload | Reset | +5V | GND | GND | Vin | C0 | C1 | C2 | C3 | C4 | C5 | Vin | Metaboard v1.0 | 5 | 4 | 3 | 2 | 1 | 0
